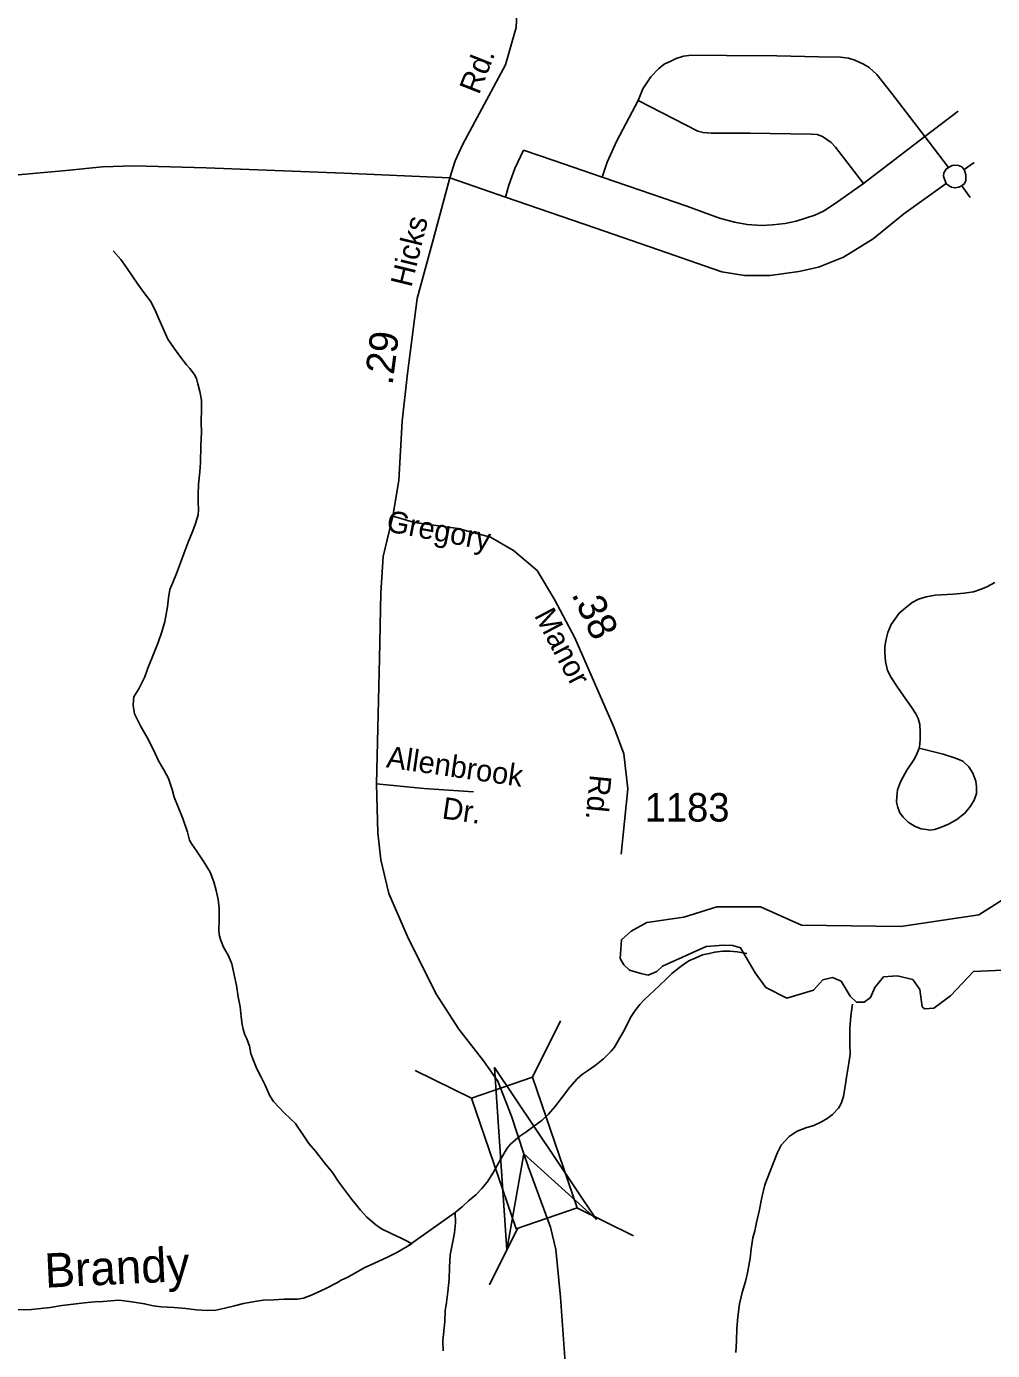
# Model space of a CAD drawing. Extents: x 2126262 to 2293712, y 749403 to 919119.
# Drawn here: x 2158706 to 2162936, y 838902 to 844700 of the extents above; entities that cross this region are included whole.
import ezdxf

# ---------------------------------------------------------------- set-up
doc = ezdxf.new("R2010")
doc.units = 0
for name, color, linetype in [('Exist Hydrographic Creek Single Shore', 7, 'Continuous'), ('Exist Hydrographic Creek Single Shore Label', 7, 'Continuous'), ('Exist Hydrographic Misc Water Feature', 7, 'Continuous'), ('Exist Hydrographic Pond Over 1500 Sq Ft', 7, 'Continuous'), ('Exist Road Non-System Type 51', 7, 'Continuous'), ('Exist Road Non-System Type 51 Label', 7, 'Continuous'), ('Exist Road Secondary Mileage Hundredths English Label', 7, 'Continuous'), ('Exist Road Secondary Structure Standard Bridge Attributed CELL', 7, 'Continuous'), ('Exist Road Secondary Structure Standard Bridge CELL', 7, 'Continuous'), ('Exist Road Secondary Type 51 Attributed', 7, 'Continuous'), ('Exist Road Secondary Type 51 Label', 7, 'Continuous'), ('Exist Road Secondary Type 51 Number Label', 7, 'Continuous')]:
    doc.layers.add(name, color=color, linetype=linetype)

msp = doc.modelspace()

# ---------------------------------------------------------------- linework, layer by layer
at = {"layer": 'Exist Hydrographic Creek Single Shore'}
msp.add_line((2160582.1, 839506.6), (2160373, 839357.4), dxfattribs=at)
for points in [[(2160582.1, 839506.6), (2160614.1, 839532.7), (2160641.8, 839556.9), (2160673.6, 839583), (2160699.6, 839611.2), (2160723.4, 839639.3), (2160751.1, 839683.5), (2160782.9, 839741.6), (2160810.6, 839787.8), (2160824.3, 839805.8), (2160846.2, 839824), (2160866.1, 839840.1), (2160892, 839858.2), (2160925.8, 839882.4), (2160963.7, 839910.6), (2160991.6, 839936.8), (2161019.3, 839968.9), (2161053.1, 840013.1), (2161084.7, 840055.3), (2161116.5, 840091.4), (2161140.5, 840111.6), (2161166.3, 840129.7), (2161196.3, 840149.9), (2161232.1, 840180), (2161266, 840212.2), (2161279.7, 840230.3), (2161297.6, 840260.4), (2161325.2, 840308.6), (2161351.1, 840360.6), (2161370.8, 840390.8), (2161390.9, 840416.9), (2161410.5, 840437), (2161454.2, 840479.2), (2161478.4, 840501.4), (2161506.1, 840527.6), (2161532.1, 840553.7), (2161571.7, 840585.8), (2161605.5, 840608), (2161633.6, 840620.2), (2161665.6, 840634.4), (2161695.4, 840640.5), (2161719.3, 840646.7), (2161755.2, 840650.9), (2161785.4, 840651.1), (2161817.4, 840647.3), (2161851.4, 840641.4), (2161860.5, 840640.3)], [(2161811.2, 838893.7), (2161815.1, 838943.7), (2161816.5, 838997.7), (2161820.2, 839049.6), (2161828, 839105.7), (2161839.7, 839155.7), (2161853.7, 839203.8), (2161863.3, 839241.8), (2161874.8, 839305.9), (2161878.5, 839347.9), (2161886.3, 839396), (2161894.3, 839426), (2161902, 839462.1), (2161913.7, 839512.1), (2161925.2, 839572.1), (2161939, 839628.2), (2161958.8, 839680.3), (2161974.6, 839720.4), (2161994.3, 839768.5), (2162010.1, 839800.5), (2162045.8, 839838.7), (2162079.8, 839862.9), (2162117.6, 839877.1), (2162153.6, 839887.3), (2162187.5, 839903.5), (2162211.3, 839917.7), (2162235.3, 839935.8), (2162261.1, 839963.9), (2162273, 839984), (2162282.8, 840014.1), (2162290.6, 840060), (2162298.2, 840108.1), (2162306, 840160.1), (2162311.7, 840200.2), (2162311.5, 840244.1), (2162311.3, 840268.1), (2162311.1, 840314.1), (2162314.8, 840366.1), (2162320.6, 840410.2), (2162322.7, 840418.2)], [(2160529.6, 838900.4), (2160529.2, 838942.4), (2160533.1, 838988.4), (2160536.8, 839028.4), (2160538.7, 839076.4), (2160544.4, 839112.4), (2160550.1, 839158.5), (2160555.9, 839214.5), (2160557.5, 839266.5), (2160561, 839320.5), (2160570.9, 839372.6), (2160580.5, 839416.6), (2160584.4, 839460.6), (2160582.1, 839506.6)], [(2158663, 839079.8), (2158727, 839082.2), (2158808.8, 839090.7), (2158860.7, 839099), (2158972.9, 839111.6), (2159004.9, 839115.8), (2159040.8, 839116), (2159074.6, 839120.1), (2159110.5, 839122.3), (2159166.7, 839114.7), (2159222.8, 839107), (2159260.8, 839097.2), (2159294.8, 839093.4), (2159322.9, 839091.6), (2159352.8, 839089.7), (2159402.9, 839086), (2159448.8, 839080.3), (2159496.8, 839076.5), (2159534.7, 839078.8), (2159574.7, 839087), (2159616.5, 839097.2), (2159656.5, 839107.5), (2159714.6, 839117.8), (2159742.6, 839121.9), (2159788.6, 839124.2), (2159834.3, 839126.4), (2159892.3, 839126.8), (2159918.4, 839130.9), (2159956.3, 839145.1), (2160016, 839173.4), (2160068.1, 839199.7), (2160083.9, 839209.8), (2160109.9, 839221.9), (2160145.8, 839242.1), (2160183.5, 839264.4), (2160229.6, 839284.6), (2160283.4, 839308.9), (2160327, 839331.1), (2160373, 839357.4), (2160392.9, 839369.5)]]:
    msp.add_lwpolyline(points, dxfattribs=at)
at = {"layer": 'Exist Hydrographic Misc Water Feature'}
for points in [[(2159084.8, 843717), (2159119.1, 843679.3), (2159143.1, 843645.4), (2159193.5, 843571.8), (2159223.9, 843529.9), (2159248.1, 843498), (2159268.2, 843460.2), (2159284.4, 843420.2), (2159302.6, 843380.3), (2159324.7, 843330.5), (2159351, 843292.7), (2159381.3, 843250.9), (2159405.5, 843219), (2159421.5, 843203.1), (2159439.8, 843177.2), (2159449.8, 843159.2), (2159456, 843135.3), (2159464, 843101.4), (2159472.4, 843063.4), (2159472.6, 843027.4), (2159470.7, 842965.4), (2159471.2, 842923.4), (2159469.5, 842863.4), (2159467.9, 842791.5), (2159464, 842749.4), (2159458.2, 842695.4), (2159456.6, 842649.4), (2159456.8, 842617.4), (2159459.1, 842585.5), (2159457, 842561.5), (2159445.3, 842523.4), (2159433.6, 842491.3), (2159413.7, 842441.2), (2159396.1, 842395.2), (2159380.3, 842351), (2159362.5, 842305), (2159346.9, 842264.9), (2159333.2, 842234.9), (2159327.2, 842198.8), (2159323.5, 842158.8), (2159311.8, 842094.7), (2159298.1, 842048.7), (2159282.3, 842002.6), (2159264.5, 841958.5), (2159237, 841890.3), (2159223.2, 841852.3), (2159197.6, 841800.2), (2159183.5, 841776.1), (2159175.9, 841764), (2159173.8, 841752), (2159172, 841726), (2159178.1, 841690.1), (2159206.6, 841634.3), (2159234.7, 841586.4), (2159261, 841532.6), (2159283.3, 841484.7), (2159307.5, 841444.9), (2159327.8, 841407), (2159344, 841359.1), (2159352, 841325.2), (2159390.6, 841231.4), (2159411.1, 841171.5), (2159419.3, 841137.6), (2159429.3, 841119.6), (2159449.6, 841089.8), (2159481.8, 841042), (2159510.1, 840996.2), (2159526.3, 840954.2), (2159536.4, 840916.3), (2159544.6, 840876.4), (2159548.9, 840838.4), (2159549.1, 840786.4), (2159547.2, 840746.4), (2159549.5, 840724.4), (2159555.6, 840702.5), (2159567.7, 840668.5), (2159590.1, 840630.6), (2159604.2, 840594.8), (2159614.5, 840546.8), (2159624.7, 840500.9), (2159633.1, 840451), (2159641.4, 840407), (2159645.7, 840363.1), (2159649.8, 840329.1), (2159653.9, 840309.2), (2159662.1, 840285.1), (2159670.1, 840267.2), (2159682.4, 840235.3), (2159688.3, 840203.3), (2159696.5, 840179.4), (2159714.8, 840135.6), (2159731, 840101.6), (2159751.1, 840063.7), (2159771.4, 840017.9), (2159787.6, 839992), (2159809.9, 839968.1), (2159833.9, 839942.2), (2159862, 839916.4), (2159884.1, 839896.5), (2159894, 839880.6)], [(2159894, 839880.6), (2159906.3, 839860.7), (2159942.6, 839808.9), (2159970.9, 839775), (2160011.1, 839723.3), (2160045.3, 839681.5), (2160073.6, 839639.6), (2160099.6, 839603.9), (2160129.8, 839564), (2160150.1, 839538.1), (2160168.1, 839516.2), (2160196.2, 839486.4), (2160234.6, 839452.6), (2160260.6, 839434.8), (2160302.8, 839415), (2160346.7, 839393.3), (2160374.8, 839379.4), (2160392.9, 839369.5)]]:
    msp.add_lwpolyline(points, dxfattribs=at)
at = {"layer": 'Exist Hydrographic Pond Over 1500 Sq Ft'}
msp.add_lwpolyline([(2163206.2, 841019.3), (2162875.9, 840810.6), (2162534, 840758.4), (2162099.4, 840764.2), (2161919.7, 840845.4), (2161728.5, 840845.4), (2161583.6, 840799), (2161421.3, 840775.8), (2161353.6, 840738.8), (2161311.2, 840700.4), (2161305.4, 840619.2), (2161320.6, 840590.3), (2161346, 840567), (2161395.5, 840553.5), (2161427.2, 840545.9), (2161465.2, 840562.4), (2161490.9, 840584.4), (2161682.1, 840671.4), (2161757.7, 840676.6), (2161798.3, 840675.4), (2161832.8, 840665.6), (2161896.5, 840555.4), (2161942.9, 840491.6), (2162035.6, 840445.2), (2162151.5, 840480), (2162192.7, 840525.9), (2162235.7, 840535.4), (2162272.6, 840519), (2162312.2, 840453.6), (2162339.7, 840427.8), (2162374.1, 840427), (2162400.8, 840448.5), (2162420.5, 840491.5), (2162458.7, 840538), (2162518.6, 840542.3), (2162586.2, 840526.4), (2162617.5, 840482.9), (2162627.8, 840407.2), (2162638.3, 840398.9), (2162679.4, 840401.2), (2162751.6, 840454.5), (2162852.7, 840561.2), (2162980.2, 840567)], dxfattribs=at)
at = {"layer": 'Exist Road Non-System Type 51'}
for p, q in [((2162639.2, 844218.1), (2162786, 844328.7)), ((2162371, 844013.2), (2162639.2, 844218.1)), ((2162742.8, 844082.5), (2162639.2, 844218.1)), ((2162812.1, 844073.3), (2162855.3, 844105)), ((2160559, 844037.4), (2160802.8, 843953.3)), ((2162801.2, 844002.9), (2162838.1, 843951.9))]:
    msp.add_line(p, q, dxfattribs=at)
for points in [[(2162639.2, 844218.1), (2162494.2, 844407.1), (2162429.6, 844490), (2162396.2, 844520.1), (2162371.2, 844535.7), (2162333.4, 844552.4), (2162305.5, 844561.3), (2162270.5, 844566.3), (2162175.6, 844567.9), (2161992, 844571.3), (2161770.8, 844573.5), (2161617.5, 844574.6), (2161581.9, 844570.2), (2161550.1, 844560.7), (2161526.8, 844548.5), (2161498.4, 844534.6), (2161473.3, 844515.1), (2161439.1, 844480), (2161405.2, 844426.6), (2161383.7, 844376.2)], [(2161226.4, 844039.9), (2161248.8, 844106.1), (2161290, 844199.6), (2161383.7, 844376.2)], [(2161383.7, 844376.2), (2161645.8, 844241.9), (2161668.1, 844235.7), (2161703.2, 844233), (2161873.4, 844233), (2162141.4, 844229.1), (2162168.1, 844226.8), (2162190.9, 844217.9), (2162210.9, 844205.7), (2162229.3, 844191.8), (2162247.7, 844172.3), (2162371, 844013.2)], [(2160802.8, 843953.3), (2160817.3, 844004.8), (2160844, 844078.3), (2160881.3, 844159.1)], [(2161226.4, 844039.9), (2161015.1, 844113.3), (2160881.3, 844159.1)], [(2162742.8, 844082.5), (2162732.9, 844076), (2162722.3, 844059.3), (2162721.8, 844045.4), (2162725.1, 844032.1), (2162733.5, 844013.2)], [(2162812.1, 844073.3), (2162801.3, 844084.9), (2162786.9, 844091.1), (2162769.6, 844092.7), (2162758.5, 844091.1), (2162742.8, 844082.5)], [(2162801.2, 844002.9), (2162812.5, 844013.2), (2162818.6, 844025.4), (2162818.6, 844036), (2162818.6, 844049.9), (2162815.2, 844064.9), (2162812.1, 844073.3)], [(2160802.8, 843953.3), (2161194, 843819), (2161472.8, 843722.1), (2161674.2, 843652), (2161751, 843625.3), (2161849, 843609.7), (2161962.5, 843609.7), (2162088.2, 843627.5), (2162173.4, 843646.5), (2162283.6, 843689.9), (2162413.2, 843770), (2162547.9, 843880.2), (2162733.5, 844013.2)], [(2162371, 844013.2), (2162247.1, 843924.7), (2162195.4, 843891.3), (2162157, 843874), (2162116.9, 843860.7), (2162075.7, 843847.3), (2162028.1, 843837.9), (2161971.9, 843831.2), (2161924.6, 843829), (2161861.8, 843832.9), (2161805.3, 843842.9), (2161739.6, 843861.2), (2161597.2, 843913), (2161392.1, 843983.1), (2161226.4, 844039.9)], [(2162733.5, 844013.2), (2162743.5, 844003.7), (2162755.7, 843996.5), (2162770.7, 843993.1), (2162788, 843996.5), (2162801.3, 844002.6)], [(2162946.6, 842265), (2162911.5, 842245.9), (2162886.6, 842235.7), (2162852.7, 842224.8), (2162811.3, 842219.1), (2162763.4, 842214), (2162684.6, 842209.5), (2162645, 842202.5), (2162611.8, 842191.6), (2162583.7, 842177.6), (2162553.1, 842153.3), (2162527.6, 842131), (2162509.7, 842106.1), (2162492.5, 842081.2), (2162477.8, 842046.1), (2162469.2, 842011), (2162463.5, 841982.9), (2162463.5, 841956.8), (2162466.6, 841919.8), (2162475.6, 841879.6), (2162491.5, 841849.6), (2162519.6, 841807.5), (2162556, 841754.5), (2162580.9, 841719.4), (2162600, 841690), (2162609.6, 841669), (2162617.9, 841644.1), (2162619.2, 841610.3), (2162619.2, 841580.3), (2162617.9, 841557.9), (2162614.7, 841540.1)], [(2160238.1, 841383.8), (2160445.1, 841363), (2160662.7, 841349)]]:
    msp.add_lwpolyline(points, dxfattribs=at)
msp.add_lwpolyline([(2162614.7, 841540.1), (2162719.4, 841513.9), (2162773.6, 841496.7), (2162806.2, 841482.6), (2162832.6, 841458.4), (2162849.9, 841430.3), (2162862, 841395.2), (2162865.8, 841370.9), (2162865.2, 841340.9), (2162855, 841312.2), (2162839.7, 841286.1), (2162814.8, 841254.8), (2162779.7, 841226.7), (2162743.6, 841206.3), (2162708.5, 841192.2), (2162682.3, 841184), (2162663.2, 841181.4), (2162645.3, 841183.3), (2162623, 841185.9), (2162597.5, 841196.1), (2162566.8, 841215.2), (2162543.9, 841237.6), (2162529.8, 841257.3), (2162520.9, 841280.3), (2162515.8, 841302.7), (2162517.1, 841328.8), (2162520.2, 841357.5), (2162533, 841392.6), (2162561.1, 841443.7), (2162591.1, 841489), (2162601.3, 841508.1)], close=True, dxfattribs=at)
at = {"layer": 'Exist Road Secondary Structure Standard Bridge Attributed CELL'}
msp.add_lwpolyline([(2160808.6, 839343.1), (2160754.8, 840141.3), (2161200.5, 839476.9), (2160884.1, 839762.7)], close=True, dxfattribs=at)
at = {"layer": 'Exist Road Secondary Structure Standard Bridge CELL'}
for p, q in [((2161043.4, 840346.4), (2160921.8, 840098.6)), ((2160406.9, 840128.8), (2160654.7, 840007.3)), ((2161116.1, 839526.2), (2161363.9, 839404.7)), ((2160855, 839437), (2160733.4, 839189.2))]:
    msp.add_line(p, q, dxfattribs=at)
msp.add_lwpolyline([(2160921.8, 840098.6), (2161117.3, 839526.7), (2160850.2, 839435.3), (2160654.7, 840007.3)], close=True, dxfattribs=at)
at = {"layer": 'Exist Road Secondary Type 51 Attributed'}
for points in [[(2160861, 844933), (2160849.8, 844696.3), (2160802.4, 844531.6), (2160616.7, 844185.1), (2160583.3, 844111.6), (2160559, 844037.4)], [(2156042.3, 842088.7), (2156096.6, 842142.9), (2156163.3, 842227.5), (2156245.7, 842354.4), (2156326.3, 842508.5), (2156623, 843081.1), (2156811.7, 843432.6), (2156920.5, 843636.4), (2157018.1, 843759.3), (2157207.8, 843871), (2157330.6, 843910.1), (2157834.1, 843964.5), (2158360.2, 844022.6), (2158878.8, 844069.2), (2159039.1, 844086.1), (2159177.1, 844089.4), (2159492.1, 844080.5), (2160095.1, 844058), (2160559, 844037.4)], [(2160559, 844037.4), (2160486.3, 843765.6), (2160416.6, 843508.7), (2160373.3, 843180.6), (2160350.5, 842972.1), (2160336.4, 842712.3), (2160309.9, 842555.9)], [(2160309.9, 842555.9), (2160268.1, 842378.6), (2160257, 842219.5), (2160251.4, 841931.8), (2160238.1, 841383.8), (2160243.7, 841168.8), (2160257.6, 841051.1), (2160292.5, 840903.1), (2160373.4, 840714.6), (2160498.3, 840465.4), (2160598.7, 840309), (2160706.1, 840170.8), (2160769.6, 840082.1), (2160829.6, 839928.5), (2160884.1, 839762.7)], [(2160309.9, 842555.9), (2160404.1, 842527.3), (2160593.9, 842502.2), (2160737.5, 842464.5), (2160838, 842405.9), (2160941.9, 842317.2), (2161017.3, 842191.5), (2161106.5, 842022.6), (2161278.8, 841629.5), (2161320.7, 841515), (2161338.1, 841362.2), (2161310.2, 841075.9)], [(2160884.1, 839762.7), (2160902.1, 839707.9), (2161000.5, 839441.9), (2161022.8, 839344.2), (2161043.7, 839136.1), (2161069.5, 838787.8), (2161086.3, 838539.3), (2161090.4, 838357.6), (2161090.4, 837926.2), (2161083.4, 837638.2), (2161086.2, 837488.8), (2161116.9, 837036.2), (2161137.8, 836766.2), (2161130.8, 836573.6), (2161107.1, 836424.2), (2161044.3, 836177.9), (2160963.4, 835902.8), (2160877.6, 835607.5)]]:
    msp.add_lwpolyline(points, dxfattribs=at)

# ---------------------------------------------------------------- texts
at = {"layer": 'Exist Hydrographic Creek Single Shore Label'}
msp.add_text('Brandy', height=150, rotation=2.73351, dxfattribs=at).set_placement((2158787.9, 839176.8))
at = {"layer": 'Exist Road Non-System Type 51 Label'}
for s, p in [('Allenbrook', (2160277.9, 841456.2)), ('Dr.', (2160521.7, 841232.4))]:
    msp.add_text(s, height=95, rotation=351.76722, dxfattribs=at).set_placement(p)
at = {"layer": 'Exist Road Secondary Mileage Hundredths English Label'}
for s, rotation, p in [('.29', 82.80689, (2160308.2, 843126.7)), ('.38', 294.99086, (2161090.5, 842214.7))]:
    msp.add_text(s, height=125, rotation=rotation, dxfattribs=at).set_placement(p)
at = {"layer": 'Exist Road Secondary Type 51 Label'}
for s, rotation, p in [('Rd.', 68.49206, (2160686.7, 844398.1)), ('Hicks', 76.24601, (2160390.7, 843554.6)), ('Gregory', 349.31038, (2160277.2, 842490)), ('Manor', 297.83519, (2160927, 842121.3)), ('Rd.', 264.41356, (2161173.1, 841426.4))]:
    msp.add_text(s, height=95, rotation=rotation, dxfattribs=at).set_placement(p)
at = {"layer": 'Exist Road Secondary Type 51 Number Label'}
msp.add_text('1183', height=125, dxfattribs=at).set_placement((2161412.3, 841218.3))

doc.saveas('drawing.dxf')
